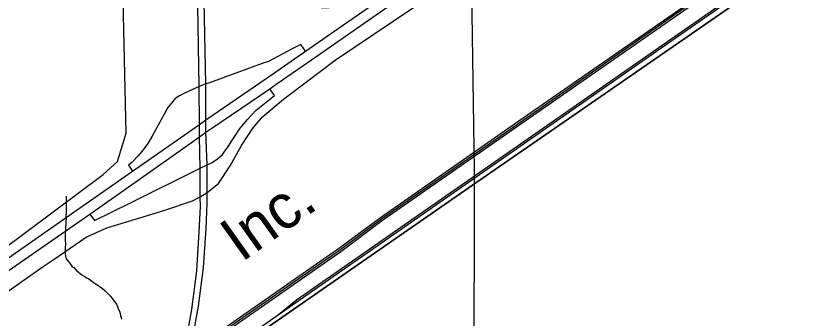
# Model space of a CAD drawing. Extents: x 0 to 44.3, y 0 to 22.
# Drawn here: x 3.268 to 4.286, y 17.715 to 18.099 of the extents above; entities that cross this region are included whole.
import ezdxf

# ---------------------------------------------------------------- set-up
doc = ezdxf.new("R2010")
doc.units = 0
for name, color, linetype in [('GM_X_Corporation', 7, 'Continuous'), ('GM_X_County_Road', 7, 'Continuous'), ('GM_X_Interchange_Ramps', 7, 'Continuous'), ('GM_X_Minor_River', 7, 'Continuous'), ('GM_X_Rail_Line', 7, 'Continuous'), ('GM_X_Rail_Line_Text', 7, 'Continuous'), ('GM_X_State_Route', 7, 'Continuous')]:
    doc.layers.add(name, color=color, linetype=linetype)

msp = doc.modelspace()

# ---------------------------------------------------------------- linework, layer by layer
at = {"layer": 'GM_X_Corporation'}
for points in [[(3.4718, 17.6223), (3.8489, 17.8842), (4.3666, 18.2423), (4.0871, 18.2389), (4.0851, 18.4197), (3.9105, 18.4164), (3.9018, 18.714), (3.8995, 18.714), (3.8965, 18.8374), (4.5061, 18.834)], [(4.5061, 18.834), (3.8965, 18.8374), (3.8995, 18.714), (3.9018, 18.714), (3.9105, 18.4164), (4.0851, 18.4197), (4.0871, 18.2389), (4.3666, 18.2423), (3.8489, 17.8842), (3.4718, 17.6223)]]:
    msp.add_lwpolyline(points, dxfattribs=at)
at = {"layer": 'GM_X_County_Road'}
for p, q in [((3.8515, 17.8286), (3.8516, 17.8788)), ((3.8503, 17.3263), (3.8515, 17.8286))]:
    msp.add_line(p, q, dxfattribs=at)
for points in [[(3.8516, 17.8788), (3.8517, 17.9029), (3.8478, 18.1604), (3.848, 18.1861), (3.8476, 18.2026), (3.847, 18.2313), (3.8459, 18.3646)], [(3.0458, 17.6679), (3.2484, 17.7998), (3.3789, 17.8978), (3.3973, 17.9143), (3.4082, 17.9504), (3.4042, 18.1384), (3.4989, 18.1388), (3.5072, 18.1389), (3.531, 18.1402), (3.544, 18.1394), (3.5547, 18.1376), (3.565, 18.1354), (3.5929, 18.1271), (3.6372, 18.1137), (3.6503, 18.1107), (3.6624, 18.1098), (3.6753, 18.1111), (3.6835, 18.1133), (3.6906, 18.1166), (3.706, 18.1274), (3.7507, 18.1609), (3.7968, 18.1955), (3.847, 18.2313)], [(3.6169, 17.9999), (3.6741, 18.0433), (3.8478, 18.1604)], [(3.3164, 17.7899), (3.3572, 17.818), (3.3838, 17.8295), (3.4256, 17.8425), (3.4576, 17.8523), (3.4925, 17.8641), (3.5025, 17.8692), (3.5112, 17.8745), (3.5259, 17.8862), (3.5406, 17.9085), (3.5549, 17.9346), (3.563, 17.9469), (3.57, 17.957), (3.5818, 17.971), (3.6086, 17.9936), (3.6169, 17.9999)], [(2.6685, 17.3171), (2.7047, 17.3465), (2.7522, 17.3814), (2.7811, 17.3981), (2.8702, 17.4669), (2.8757, 17.4712), (2.94, 17.5217), (2.9587, 17.5389), (3.122, 17.6526), (3.2753, 17.7614), (3.3028, 17.7805), (3.3164, 17.7899)]]:
    msp.add_lwpolyline(points, dxfattribs=at)
at = {"layer": 'GM_X_Interchange_Ramps'}
for p, q in [((3.4128, 17.8611), (3.5025, 17.9056)), ((3.5025, 17.9056), (3.5112, 17.9098))]:
    msp.add_line(p, q, dxfattribs=at)
for points in [[(3.6365, 18.0546), (3.6305, 18.0631), (3.6196, 18.0575), (3.5895, 18.0417), (3.5813, 18.0388)], [(3.5813, 18.0388), (3.5145, 18.0145), (3.5095, 18.0129)], [(3.5095, 18.0129), (3.5011, 18.0096), (3.4827, 18.0012), (3.4761, 17.9978), (3.4701, 17.9939), (3.4661, 17.9885), (3.4615, 17.9828), (3.4414, 17.9463), (3.4349, 17.9358), (3.4294, 17.9284), (3.4236, 17.9214), (3.4158, 17.9133), (3.4111, 17.9093), (3.4163, 17.9017)], [(3.5112, 17.9098), (3.5176, 17.9127), (3.5244, 17.9175), (3.531, 17.923), (3.5373, 17.9322), (3.5533, 17.9566), (3.5625, 17.9678), (3.5739, 17.9794), (3.5969, 17.9983), (3.591, 18.0069)], [(3.3622, 17.8472), (3.3679, 17.8389), (3.4128, 17.8611)]]:
    msp.add_lwpolyline(points, dxfattribs=at)
at = {"layer": 'GM_X_Minor_River'}
msp.add_lwpolyline([(3.3317, 17.8701), (3.3318, 17.8652), (3.3318, 17.8625), (3.3318, 17.8602), (3.3319, 17.8576), (3.3319, 17.8557), (3.3319, 17.853), (3.3319, 17.8504), (3.332, 17.8485), (3.3316, 17.8462), (3.3316, 17.8435), (3.3317, 17.8408), (3.3313, 17.8386), (3.3313, 17.8363), (3.3314, 17.834), (3.331, 17.831), (3.331, 17.8279), (3.3311, 17.8253), (3.3307, 17.8226), (3.3308, 17.8195), (3.3308, 17.8173), (3.3304, 17.8146), (3.3309, 17.8085), (3.3306, 17.8047), (3.3306, 17.8013), (3.3306, 17.7986), (3.3306, 17.7963), (3.3311, 17.7937), (3.3319, 17.7903), (3.3334, 17.788), (3.3365, 17.7846), (3.3384, 17.782), (3.3396, 17.7801), (3.3415, 17.779), (3.3445, 17.7759), (3.3472, 17.7737), (3.3503, 17.7711), (3.3533, 17.7692), (3.3553, 17.7681), (3.3579, 17.7662), (3.3602, 17.7651), (3.3629, 17.7632), (3.366, 17.7609), (3.3679, 17.7594), (3.3698, 17.7583), (3.3725, 17.7561), (3.3751, 17.7546), (3.3782, 17.7523), (3.3809, 17.7501), (3.384, 17.747), (3.3866, 17.7444), (3.3889, 17.7421), (3.3905, 17.7399), (3.3928, 17.7365), (3.3951, 17.7338), (3.3963, 17.7316), (3.3971, 17.7297), (3.3982, 17.7266), (3.3998, 17.7236), (3.4006, 17.7206), (3.401, 17.7175), (3.4018, 17.7157), (3.4022, 17.7134)], dxfattribs=at)
at = {"layer": 'GM_X_Rail_Line'}
for points in [[(3.5999, 17.7177), (3.625, 17.738), (4.1101, 18.0759), (4.3321, 18.2303), (4.7082, 18.4918), (4.7212, 18.4999), (4.7363, 18.509), (4.7506, 18.5163), (4.7658, 18.5236), (4.7826, 18.5303), (4.7956, 18.5351), (4.8104, 18.5394), (4.8276, 18.5439), (4.8439, 18.5472), (4.8582, 18.5495), (4.8772, 18.5516), (4.8966, 18.5527), (4.9196, 18.5531), (4.938, 18.5533), (5.0014, 18.5517)], [(3.5315, 17.7008), (3.6785, 17.8033), (3.732, 17.843), (3.9081, 17.9659), (4.1306, 18.1209), (4.1964, 18.1669), (4.2494, 18.2036), (4.3197, 18.2538)], [(3.5329, 17.6989), (3.6799, 17.8014), (3.7333, 17.8412), (3.9094, 17.964), (4.1319, 18.119), (4.1977, 18.165), (4.2507, 18.2017), (4.321, 18.2519)], [(3.5342, 17.697), (3.6813, 17.7995), (3.7347, 17.8393), (3.9107, 17.9621), (4.1332, 18.1171), (4.199, 18.1631), (4.2521, 18.1998), (4.3224, 18.25)], [(3.4981, 17.6468), (4.1115, 18.074), (4.3334, 18.2284)]]:
    msp.add_lwpolyline(points, dxfattribs=at)
at = {"layer": 'GM_X_State_Route'}
msp.add_line((3.599, 18.0125), (3.6071, 18.0181), dxfattribs=at)
for points in [[(3.5011, 18.0096), (3.4989, 18.1388), (3.4946, 18.4146), (3.4891, 18.694), (3.4884, 18.7223), (3.4871, 18.7484), (3.4851, 18.7692), (3.4759, 18.8567), (3.4711, 18.9003), (3.4674, 18.946), (3.4669, 18.9751), (3.4698, 19.0727), (3.4704, 19.1056), (3.4763, 19.2627), (3.4788, 19.3987), (3.4768, 19.4572), (3.4741, 19.5262), (3.4704, 19.5646), (3.4627, 19.6372), (3.4577, 19.6789), (3.4526, 19.7137), (3.4452, 19.7604), (3.4366, 19.8072), (3.4303, 19.8479)], [(3.5956, 18.0264), (3.6365, 18.0546), (3.7497, 18.1338), (3.8476, 18.2026), (3.9658, 18.2834), (3.9877, 18.2997), (4.0114, 18.3184), (4.0322, 18.3356), (4.0512, 18.3526), (4.0717, 18.3711), (4.0848, 18.384), (4.1026, 18.403), (4.1201, 18.4212), (4.1677, 18.4698)], [(3.6071, 18.0181), (3.6441, 18.0437), (3.7642, 18.1275), (3.848, 18.1861), (3.9739, 18.2749), (3.9975, 18.2918), (4.0228, 18.312), (4.045, 18.3301), (4.0631, 18.3471), (4.0812, 18.3635), (4.0979, 18.3794), (4.0993, 18.3808)], [(3.5095, 18.0129), (3.5072, 18.1389), (3.5067, 18.1757)], [(2.5977, 17.3184), (2.7078, 17.3998), (2.8419, 17.499), (2.9594, 17.5836), (3.0397, 17.6398), (3.1845, 17.7401), (3.3531, 17.8578), (3.4163, 17.9017), (3.5014, 17.9614), (3.5098, 17.9673), (3.5956, 18.0264)], [(3.5025, 17.8692), (3.5025, 17.9056), (3.5015, 17.9455), (3.5014, 17.9614), (3.5011, 18.0096)], [(3.5098, 17.957), (3.5098, 17.9673), (3.5095, 18.0129)], [(3.5172, 17.9565), (3.591, 18.0069), (3.599, 18.0125)], [(3.3622, 17.8472), (3.4237, 17.8903), (3.5015, 17.9455), (3.5098, 17.9514), (3.5172, 17.9565)], [(3.5112, 17.8745), (3.5112, 17.9098), (3.5098, 17.9514), (3.5098, 17.957)], [(3.4762, 17.6213), (3.4849, 17.6537), (3.4932, 17.6899), (3.5005, 17.73), (3.5068, 17.7791), (3.5099, 17.8287), (3.5114, 17.8609), (3.5112, 17.8745)], [(3.3895, 17.1913), (3.3848, 17.2012), (3.3858, 17.2265), (3.3874, 17.2638), (3.3911, 17.3057), (3.3945, 17.3385), (3.3989, 17.3639), (3.4037, 17.3894), (3.4173, 17.4409), (3.4437, 17.5374), (3.463, 17.6056), (3.4757, 17.6515), (3.4845, 17.6856), (3.4918, 17.7257), (3.4981, 17.7749), (3.5012, 17.8244), (3.5027, 17.8567), (3.5025, 17.8692)], [(2.6933, 17.3719), (2.7153, 17.3882), (2.8502, 17.4889), (2.9594, 17.5667), (3.0471, 17.6281), (3.1952, 17.7316), (3.3622, 17.8472)]]:
    msp.add_lwpolyline(points, dxfattribs=at)

# ---------------------------------------------------------------- texts
at = {"layer": 'GM_X_Rail_Line_Text'}
msp.add_text('Inc.', height=0.05663, rotation=35.3705, dxfattribs=at).set_placement((3.555, 17.785))

doc.saveas('drawing.dxf')
